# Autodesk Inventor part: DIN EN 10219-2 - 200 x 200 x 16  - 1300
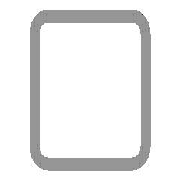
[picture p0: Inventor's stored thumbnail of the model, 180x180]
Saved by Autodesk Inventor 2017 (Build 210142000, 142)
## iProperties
Created: 2016-02
Part Number: DIN EN 10219-2 - 200 x 200 x 16  - 1300
Material: Steel, Mild
Description: Cold formed welded structural hollow sections of non-alloy and fine grain structural steel
Document SubType Name: Modeling
Standard: DIN
Designer: iusti
Standard Revision: 2006-07
Standards Organization: DIN
Language: en-US
Size Designation: 200 x 200 x 16
Categories: <MemberInstance><Categories><Category DisplayName="Structural Shapes" InternalName="089c4875-fa83-4c05-b084-43b9cc11f5ed" Mnemonic="GRDR"><CategoryParameter Dis
Stock Number: 200 x 200 x 16
Mass: 108961 g
Surface Area: 17564.1 cm^2
Volume: 13880.4 cm^3
Density: 7.85 g/cm^3
Appearance: Semi-Polished
_CCFamilyMember: 103
_CCFamilyDisplayName: DIN EN 10219-2 (Square Hollow Section - Cold Formed) - Cold formed welded structural hollow sections of non-alloy and fine grain structural steel
_FrameMemberDoc: Frame Member File
_Version: 15.0.0
_GetPNFromCC: 1
G_L: 1300.000 mm
G_W: 200.000 mm
G_H: 200.000 mm
+CEF86B8C-3238-420E-ADC4-8D9549012C8A+CUTDETAIL1: Cut
+AF8588F7-3CA6-436D-9A69-B39F8946184A+CUTDETAIL2: Cut
IsCustomPart: 1
Author: iusti
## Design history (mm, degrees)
node "Start plane"
node "End plane"
sketch "Sketch"
  geometry: L1 (-100, -52)-(-100, 52); L2 (-52, 100)-(52, 100); L3 (100, 52)-(100, -52); L4 (52, -100)-(-52, -100); L5 (-52, 84)-(52, 84); L6 (84, 52)-(84, -52); L7 (52, -84)-(-52, -84); L8 (-84, -52)-(-84, 52); L9 (0, 153.918)-(0, -153.918) reference; L10 (-153.918, 0)-(153.918, 0) reference; A1 r 48 centre (-52, -52) between (-100, -52) and (-52, -100); A2 r 48 centre (-52, 52) between (-52, 100) and (-100, 52); A3 r 48 centre (52, 52) between (100, 52) and (52, 100); A4 r 48 centre (52, -52) between (52, -100) and (100, -52); A5 r 32 centre (-52, 52) between (-52, 84) and (-84, 52); A6 r 32 centre (52, 52) between (84, 52) and (52, 84); A7 r 32 centre (52, -52) between (52, -84) and (84, -52); A8 r 32 centre (-52, -52) between (-84, -52) and (-52, -84)
  constraints: 16 end point, 16 point on circle, 8 centre point, 8 tangent, 4 parallel, 3 equal radius, 2 perpendicular, 7 other
  dimensions: "d7" = 48 radius of A1 (= G_IR); "d10" = 200 distance between parallel lines of L2 L4 (= G_H); "d11" = 200 distance between parallel lines of L1 L3 (= G_W); "d12" = 16 distance between parallel lines of L3 L6 (= G_T); "d15" = 100 distance between parallel lines of L2 L10 (= 0.5 x d10); "d16" = 100 distance between parallel lines of L9 L3 (= 0.5 x d11)
extrude "Body" new body sketch "Sketch" stored distance "d3" = 1300 (= G_L); taper "d4" = 0 deg
node "Driven Length"
  sketch "Sketch3"
    geometry: L1 (0, 0)-(10, 0) reference
    constraints: 2 end point, 1 horizontal
  workplane "Work Plane3"
  sketch "Sketch4"
    geometry: L1 (-2, 100)-(12, 100) reference; L2 (-2, 1400)-(12, 1400) reference
    dimensions: "d18" = 1300 distance between parallel lines of L1 L2 (derived)
workplane "Work Plane4"
split "Split1"
workplane "Work Plane5"
split "Split2"
body "Solid1"
other parameters: "G_W" = 200 [user parameter; used in 1 equation term], "G_H" = 200 [user parameter; used in 1 equation term], "G_T" = 16 [user parameter; used in 1 equation term], "G_IR" = 48 [user parameter; used in 1 equation term], "G_L" = 1300 (= d18) [user parameter; used in 1 equation term], "d17" = 90 deg
